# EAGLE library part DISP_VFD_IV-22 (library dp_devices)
7-segment VFD Display Dangerousprototypes.com
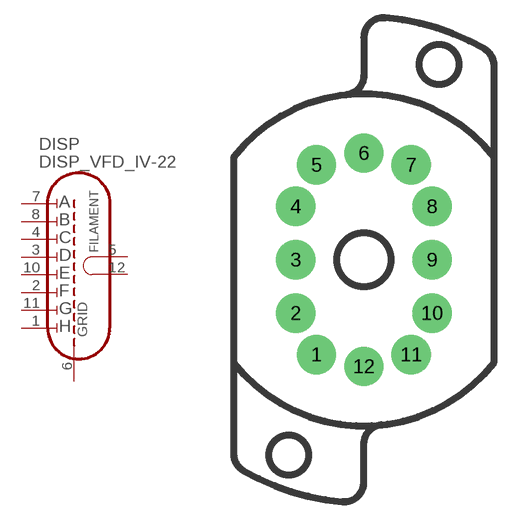
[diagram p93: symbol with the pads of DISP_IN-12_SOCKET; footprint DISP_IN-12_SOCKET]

Designator prefix DISP

## DISP_VFD_IV-22  [DISP_IN-12_SOCKET]
1  H  in
2  F  in
3  D  in
4  C  in
5  FA  pwr
6  GRID  in
7  A  in
8  B  in
10  E  in
11  G  in
12  FB  pwr

## Footprint DISP_IN-12_SOCKET (pad centres in mm)
drill 2.3 round: 1 -4,-8; 2 -5.75,-4.5; 3 -5.75,0; 4 -5.75,4.5; 5 -4,8; 6 0,9; 7 4,8; 8 5.75,4.5; 9 5.75,0; 10 5.75,-4.5; 11 4,-8; 12 0,-9
hole 3.3 at 6.35,16.5
hole 3.3 at -6.35,-16.5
